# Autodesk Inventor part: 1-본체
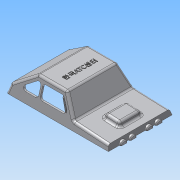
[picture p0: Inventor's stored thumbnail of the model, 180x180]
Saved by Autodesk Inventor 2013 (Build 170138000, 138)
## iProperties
Created: 2015-05
Part Number: 1-본체
Material: ABS 플라스틱
Document SubType Name: Modeling
Designer: ST
Density: 1.06 g/cm^3
Mass: 30.4732 g
Surface Area: 305.118 cm^2
Volume: 28.7483 cm^3
Author: ST
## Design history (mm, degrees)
sketch "스케치1"
  geometry: L1 (-61, 38)-(61, 38); L2 (61, 38)-(61, -38); L3 (61, -38)-(-61, -38); L4 (-61, -38)-(-61, 38); 4 further points
  constraints: 8 end point, 2 midpoint, 2 parallel, 1 coincident, 1 horizontal, 1 horizontal alignment, 1 perpendicular, 1 vertical alignment
  dimensions: "d0" = 122 distance of L1.start L1.end; "d2" = 76 distance of L1.end L2.end
extrude "돌출1" new body sketch "스케치1" distance "d3" = 30; taper "d4" = -15 deg
sketch "스케치2"
  geometry: L1 (-52.962, 30)-(52.962, 30) reference; L2 (31, 30)-(58.321, 10); L3 (61, 0)-(52.962, 30) reference; 1 further point
  constraints: 2 end point, 2 point on line
  dimensions: "d5" = 30 horizontal distance of L3.start L2.start; "d7" = 20 distance from line of L1 L2.end
extrude "돌출2" cut sketch "스케치2" stored distance "d8" = 31; taper "d9" = 0 deg
sketch "스케치3"
  geometry: L1 (-61, 0)-(-52.962, 30) reference; L2 (-59.392, 6)-(-17.392, 8.201); L3 (-61, 0)-(61, 0) reference; L4 (-52.962, 30)-(31, 30) reference; L5 (-17.392, 8.201)-(-3.771, 30); 1 further point
  constraints: 4 end point, 2 point on line
  dimensions: "d10" = 3 deg angle of L3 L2; "d11" = 6 vertical distance of L2.start L1.start; "d13" = 42 horizontal distance of L2.end L2.start; "d14" = 125 deg angle of L5 L2
extrude "돌출3" cut sketch "스케치3" stored distance "d15" = 0; taper "d16" = 0 deg
feature "쉘1" dims "d17" = 2
sketch "스케치4"
  geometry: L1 (61, 38)-(-61, 38) reference; L2 (-61, 38)-(-61, -38) reference; L3 (61, -38)-(61, 38) reference; L4 (-61, -38)-(61, -38) reference; L5 (-60, 37)-(60, 37); L6 (60, 37)-(60, -37); L7 (60, -37)-(-60, -37); L8 (-60, -37)-(-60, 37); L9 (-58.929, -35.929)-(-58.929, 35.929) reference; L10 (-58.929, 35.929)-(58.929, 35.929) reference; L11 (58.929, -35.929)-(-58.929, -35.929) reference; L12 (58.929, 35.929)-(58.929, -35.929) reference; 1 further point
  constraints: 8 end point, 3 other
  dimensions: "d18" = 1 distance between parallel lines of L1 L5
extrude "돌출4" join sketch "스케치4" distance "d19" = 1; taper "d20" = 0 deg
sketch "스케치5"
  geometry: L1 (-59.392, 6)-(-17.392, 8.201) reference; L2 (-50, 6.492)-(-48.444, 11.581); L3 (-48.444, 11.581)-(-32.106, 12.437); L4 (-32.106, 12.437)-(-30.027, 7.539); L5 (-61, 0)-(-59.392, 6) reference; 1 further point
  constraints: 6 end point, 2 point on line, 1 parallel
  dimensions: "d25" = 70 deg angle of L2 L1; "d26" = 70 deg angle of L4 L1; "d27" = 5 distance between parallel lines of L3 L1; "d29" = 20 distance of L4.end L2.start; "d31" = 11 horizontal distance of L2.start L5.start
extrude "돌출5" join sketch "스케치5" stored distance "d32" = 26; taper "d33" = 0 deg
sketch "스케치6"
  geometry: L1 (-61, 38)-(-61, -38) reference; C1 r 3 at (-40, 0); C2 r 3 at (0, -22); C3 r 3 at (40, 0); C4 r 3 at (0, 22); 2 further points
  constraints: 4 centre point, 3 equal radius, 2 horizontal alignment, 2 vertical alignment, 1 midpoint
  dimensions: "d34" = 6 diameter of C1; "d36" = 40 distance of point (0, 0) C1.centre; "d37" = 40 distance of C3.centre point (0, 0); "d38" = 22 distance of C4.centre point (0, 0); "d39" = 44 distance of C2.centre C4.centre
extrude "돌출6" join sketch "스케치6" stored distance "d40" = 26; taper "d41" = 2 deg
sketch "스케치7"
  geometry: L1 (-57.837, 4.079)-(-16.248, 6.258) reference; L2 (-48.444, 11.581)-(-32.106, 12.437) reference; L3 (-50, 6.492)-(-30.027, 7.539) reference; L4 (-50, 6.492)-(-48.444, 11.581) reference; L5 (-48.444, 11.581)-(-32.106, 12.437) reference; L6 (-32.106, 12.437)-(-30.027, 7.539) reference; L7 (-48.497, 4.568)-(-46.941, 9.657); L8 (-46.941, 9.657)-(-33.4, 10.366); L9 (-33.4, 10.366)-(-31.321, 5.468); 1 further point
  constraints: 6 end point, 2 point on line, 2 other
  dimensions: "d42" = 2 distance between parallel lines of L2 L8
extrude "돌출7" cut sketch "스케치7" stored distance "d43" = 22; taper "d44" = 0 deg
sketch "스케치10"
  geometry: C1 r 3 at (0, 0) reference; 1 further point
extrude "돌출9" join sketch "스케치10" stored distance "d47" = 22; taper "d48" = 2 deg
sketch "스케치12"
  geometry: L1 (-46.327, 9.524)-(-45, 2); L2 (-45, 2)-(-35, 2); L3 (-35, 2)-(-33.526, 10.36); L4 (-46.941, 9.657)-(-33.4, 10.366) reference; L5 (-37, 0)-(-43, 0) reference; L6 (-40, 0)-(-40, 10.02); L7 (-43, 0)-(-43.344, 9.845) reference; L8 (-37, 0)-(-36.644, 10.196) reference; L9 (30.346, 28)-(56.571, 8.802) reference; L10 (35, 2)-(45, 2); L11 (45, 2)-(47.385, 15.527); L12 (43, 0)-(37, 0) reference; L13 (40, 0)-(40, 20.933); L14 (35, 2)-(30.426, 27.942); 3 further points
  constraints: 16 end point, 7 point on line, 4 midpoint, 3 perpendicular, 1 horizontal
  dimensions: "d55" = 2 distance between parallel lines of L2 L5; "d57" = 10 distance of L1.end L2.end; "d58" = 20 deg angle of L3 L1; "d59" = 10 deg angle of L6 L1; "d61" = 10 deg angle of L13 L11; "d62" = 10 deg angle of L14 L13; "d63" = 10 distance of L10.start L10.end; "d64" = 2 distance between parallel lines of L10 L12
extrude "돌출10" join sketch "스케치12" stored distance "d65" = 2; taper "d66" = 0 deg
sketch "스케치13"
  geometry: L1 (-43, 0)-(-43.344, 9.845) reference; L2 (-37, 0)-(-36.644, 10.196) reference; L3 (-37, 0)-(-43, 0) reference; L4 (-46.941, 9.657)-(-33.4, 10.366) reference; L5 (-46.355, 9.687)-(-45, 2); L6 (-45, 2)-(-35, 2); L7 (-35, 2)-(-33.4, 10.366); L8 (-40, 0)-(-40, 10.02); L9 (-60, -1)-(60, -1) reference; 2 further points
  constraints: 8 end point, 3 point on line, 2 midpoint, 1 perpendicular
  dimensions: "d67" = 10 distance of L5.end L6.end; "d71" = 10 deg angle of L8 L5; "d73" = 2 distance between parallel lines of L6 L3
extrude "돌출11" join sketch "스케치13" stored distance "d74" = 2; taper "d75" = 0 deg
sketch "스케치14"
  geometry: L1 (-28.427, 28)-(-33.571, 8.802) reference; L2 (-30.331, 20.893)-(-27, 2); L3 (-27, 2)-(-17, 2); L4 (-17, 2)-(-12.415, 28); L5 (12.415, 28)-(17, 2); L6 (17, 2)-(27, 2); L7 (29.962, 30)-(-29.962, 30) reference; L8 (27, 2)-(30.331, 20.893); L9 (-19, 0)-(-25, 0) reference; L10 (25, 0)-(19, 0) reference; L11 (-22, 0)-(-22, 28); L12 (25.978, 28)-(18.022, 28) reference; L13 (22, 28)-(22, 0); L14 (33.571, 8.802)-(28.427, 28) reference; 5 further points; 1 other entity
  constraints: 16 end point, 5 midpoint, 4 point on line, 3 parallel, 1 horizontal, 1 perpendicular, 4 other
  dimensions: "d76" = 20 deg angle of L4 L2; "d77" = 10 distance of L2.end L3.end; "d79" = 10 distance of L5.end L6.end; "d80" = 2 distance between parallel lines of L3 L9; "d81" = 2 distance between parallel lines of L6 L10; "d82" = 10 deg angle of L11 L4
extrude "돌출12" join sketch "스케치14" stored distance "d83" = 2; taper "d84" = 0 deg
sketch "스케치15"
  geometry: C1 r 3 at (-40, 22) reference; C2 r 3 at (0, 44) reference; C3 r 3 at (0, 0) reference; C4 r 3 at (40, 22) reference; 5 further points
  constraints: 4 coincident
hole "구멍1" sketch "스케치15" at (-40, 22), (0, 44), (0, 0), (40, 22) diameter "d85" = 3.242; stored, may be unused: countersink angle "d89" = 90 deg, drill point angle "d91" = 118 deg; dims "d86" = 9, "d87" = 4, "d88" = 2, "d90" = 11
node "작업 평면1"
sketch "스케치16"
  geometry: L1 (3.771, 30)-(-31, 30) reference; L2 (17.392, 8.201)-(3.771, 30) reference; L3 (-31, 30)-(-58.321, 10) reference; L4 (0.999, 25)-(10.372, 10); L5 (10.372, 10)-(-23.628, 10); L6 (58.929, -1)-(-58.929, -1) reference; L7 (-23.628, 10)-(-23.628, 25); L8 (-25.628, 25)-(-25.628, 10); L9 (-25.628, 10)-(-53.628, 10); L10 (-49.856, 10)-(-29.365, 25); L11 (-29.365, 25)-(-25.628, 25); L12 (-23.628, 25)-(0.999, 25); L13 (-25.628, 10)-(-49.856, 10); 1 further point
  constraints: 18 end point, 5 perpendicular, 2 parallel, 1 horizontal alignment, 1 point on line
  dimensions: "d94" = 5 distance between parallel lines of L2 L4; "d96" = 34 distance of L4.end L5.end; "d97" = 28 distance of L8.end L9.end; "d98" = 5 distance between parallel lines of L3 L10; "d101" = 15 distance of L8.start L8.end; "d102" = 5 distance between parallel lines of L1 L12; "d103" = 15 distance between parallel lines of L12 L5; "d104" = 2 distance between parallel lines of L7 L8
extrude "돌출13" cut sketch "스케치16" stored distance "d105" = 2; taper "d106" = 0 deg
sketch "스케치17"
  geometry: L1 (-61, -38)-(-61, 38) reference; 2 further points
  constraints: 1 horizontal alignment, 1 other
  dimensions: "d107" = 50 distance from line of point (-11, 0) L1
feature "엠보싱1" sketch "스케치17" dims "d108" = 0.5, "d109" = 0
fillet "모깎기1" dims "d110" = 3
fillet "모깎기2" dims "d111" = 3
fillet "모깎기3" dims "d112" = 3
fillet "모깎기4" dims "d113" = 3
node "작업 평면2"
sketch "스케치18"
  geometry: A1 r 4 centre (-21, 0) between (-17, 0) and (-25, 0); A2 r 4 centre (-10, 0) between (-6, 0) and (-14, 0); A3 r 4 centre (10, 0) between (14, 0) and (6, 0); A4 r 4 centre (21, 0) between (25, 0) and (17, 0); 3 further points
  constraints: 8 point on circle, 4 centre point, 3 equal radius, 13 other
  dimensions: "d115" = 8 diameter of A1; "d117" = 10 distance of A2.centre point (0, 0); "d118" = 10 distance of A3.centre point (0, 0); "d119" = 11 distance of A4.centre A3.centre; "d120" = 11 distance of A2.centre A1.centre
extrude "돌출14" join sketch "스케치18" stored distance "d121" = 0; taper "d122" = 0 deg
chamfer "모따기1" distance "d123" = 1; stored, may be unused: second distance "d124" = 2, angle "d125" = 45 deg
fillet "모깎기5" dims "d126" = 3
fillet "모깎기6" dims "d127" = 3
fillet "모깎기7" dims "d128" = 3
fillet "모깎기8" dims "d129" = 3
node "솔리드1"
mirror "대칭1"
node "투영된 루프1"
other parameters: "d92" = -38, "d93" = 5, "d95" = 15, "d114" = 63
